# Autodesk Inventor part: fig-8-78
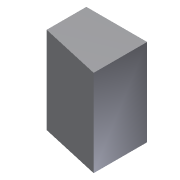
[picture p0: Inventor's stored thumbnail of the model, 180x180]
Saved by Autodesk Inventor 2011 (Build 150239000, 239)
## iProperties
Created: 2009-04
Part Number: fig-8-78
Document SubType Name: Modeling
Designer: Sham
Density: 1 g/cm^3
Author: Sham
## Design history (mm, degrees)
sketch "Sketch5"
  geometry: L1 (14, -20)-(0, -20); L2 (0, -20)-(0, 0); L3 (0, 0)-(14, 0); L4 (14, 0)-(14, -20)
  constraints: 8 end point
extrude "Extrusion2" new body sketch "Sketch5" distance "d3" = 20; taper "d4" = 0 deg
sketch "Sketch6"
  geometry: L1 (-5, 12)-(17, 7)
  constraints: 2 end point
split "Split8" sketch "Sketch6"
body "Solid2"
